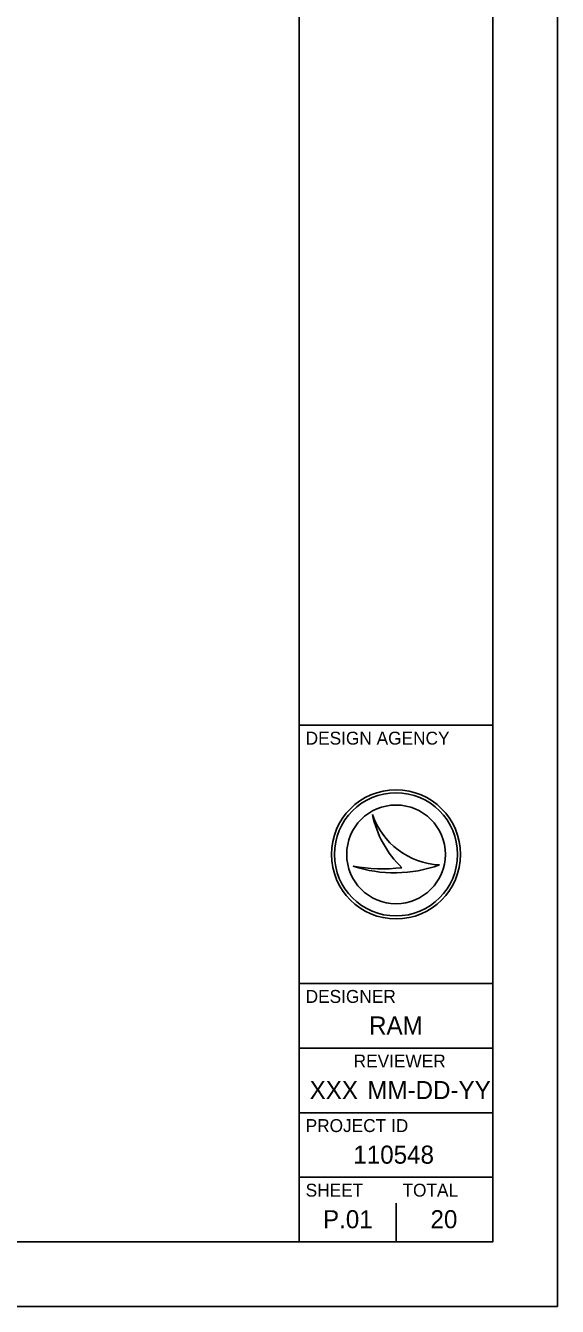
# Model space of a CAD drawing. Extents: x 0 to 34, y 0 to 22.
# Drawn here: x 29.88 to 34, y 0 to 9.92 of the extents above; entities that cross this region are included whole.
import ezdxf

# ---------------------------------------------------------------- set-up
doc = ezdxf.new("R2010")
doc.units = 0
for name, color, linetype in [('SH_Border', 7, 'Continuous'), ('SH_Cut_Line', 7, 'Continuous'), ('SH_Data', 7, 'Continuous')]:
    doc.layers.add(name, color=color, linetype=linetype)

msp = doc.modelspace()

# ---------------------------------------------------------------- linework, layer by layer
at = {"layer": 'SH_Border'}
for p, q in [((32, 0.5), (32, 21.5)), ((32, 4.5), (33.5, 4.5)), ((32, 2.5), (33.5, 2.5)), ((32, 2), (33.5, 2)), ((32, 1.5), (33.5, 1.5)), ((32, 1), (33.5, 1))]:
    msp.add_line(p, q, dxfattribs=at)
msp.add_lwpolyline([(1.5, 21.5), (33.5, 21.5), (33.5, 0.5), (1.5, 0.5)], close=True, dxfattribs=at)
at = {"layer": 'SH_Cut_Line'}
msp.add_lwpolyline([(0, 0), (34, 0), (34, 22), (0, 22)], close=True, dxfattribs=at)
at = {"layer": 'SH_Data'}
for p, q in [((32.5674, 3.8096), (32.5675, 3.8096)), ((32.75, 3.5), (32.75, 3.5)), ((32.4172, 3.4095), (32.4172, 3.4095)), ((33.0873, 3.4185), (33.0873, 3.4185)), ((32.75, 0.5), (32.75, 0.8)), ((32.375, 0.675), (32.375, 0.675))]:
    msp.add_line(p, q, dxfattribs=at)
for radius in [0.5, 0.4768, 0.4768, 0.3822]:
    msp.add_circle((32.75, 3.5), radius, dxfattribs=at)
for centre, radius, start, end in [((33.1159, 3.9976), 0.5798, 198.92567, 198.93195), ((33.3467, 3.9701), 0.7956, 191.63793, 191.64215), ((33.1159, 3.9976), 0.5798, 198.93195, 267.16574), ((33.3467, 3.9701), 0.7956, 191.64215, 226.09467), ((32.7394, 4.37), 1.0131, 251.45764, 290.08324), ((32.648, 4.6543), 1.2661, 259.49639, 259.49952), ((32.7394, 4.37), 1.0131, 251.45274, 251.45764), ((32.648, 4.6543), 1.2661, 259.49952, 276.66723)]:
    msp.add_arc(centre, radius, start, end, dxfattribs=at)

# ---------------------------------------------------------------- texts
for s, height, p in [('DESIGN AGENCY', 0.1, (32.05, 4.35)), ('DESIGNER', 0.1, (32.05, 2.35)), ('RAM', 0.14, (32.5412, 2.105)), ('REVIEWER', 0.1, (32.4218, 1.85)), ('XXX', 0.14, (32.0809, 1.605)), ('MM-DD-YY', 0.14, (32.5273, 1.605)), ('PROJECT ID', 0.1, (32.05, 1.35)), ('110548', 0.14, (32.4193, 1.105)), ('SHEET', 0.1, (32.05, 0.85)), ('TOTAL', 0.1, (32.8, 0.85)), ('P.01', 0.14, (32.1844, 0.605)), ('20', 0.14, (33.0171, 0.605))]:
    msp.add_text(s, height=height, dxfattribs=at).set_placement(p)

doc.saveas('drawing.dxf')
